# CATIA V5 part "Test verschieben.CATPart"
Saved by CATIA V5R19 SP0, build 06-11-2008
Part number: Test verschieben.1
Publications: "Scheitelpunkt"
Bounding box of the stored display mesh (mm): x 0 to 100, y 0 to 50, z 0 to 20
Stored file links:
  P:\Catia\Test\Test verschieben.CATPart
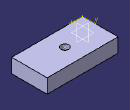
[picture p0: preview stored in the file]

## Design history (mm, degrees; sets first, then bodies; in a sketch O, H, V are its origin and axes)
Body1 (main body)
  Sketch1 on xy-plane, origin (0, 0, 0), H (1, 0, 0), V (0, 1, 0)
    line L1 (0, 50) -> (100, 50)
    line L2 (100, 50) -> (100, 0)
    line L3 (100, 0) -> (0, 0)
    line L4 (0, 0) -> (0, 50)
    length L1 = 100
    length L2 = 50
    horizontal: L1 H, L3 H
    vertical: L2 V, L4 V
    coincidence: L4 V, L3 H
  Pad1: profile Sketch1, direction (0, 0, 1), length 20
  Sketch2 on end face of Pad1, origin (0, 0, 20), H (1, 0, 0), V (0, 1, 0)
    point P1 (50, 25)
    reference projected line E1 (0, 50) -> (0, 0) from edge [face of Pad1 from Sketch1.L4 | end face of Pad1]
    distance E1 P1 = 50
    distance H P1 = 25
  Sketch3 on end face of Pad1, origin (50, 25, 20), H (1, 0, 0), V (0, 1, 0)
    point P1 (0, 0)
    reference projected point E1 (0, 0) from Sketch2.P1
    coincidence: E1 P1
  Hole1: placed by Sketch3, at (50, 25, 20) direction (0, 0, -1), diameter 6.6, through (limit type 3), counterbore diameter 11, counterbore depth 8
